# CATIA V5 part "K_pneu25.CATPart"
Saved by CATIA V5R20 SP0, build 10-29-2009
Part number: pneu 25
Publications: "rayon pneu", "largeur pneu", "rayon congé", "Plan.+100", "pneu 25"
Bounding box of the stored display mesh (mm): x 100 to 300, y 820 to 1300, z -240 to 240
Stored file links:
  G:\Khaled_CFAO_2011\SIL\SIL_GR2\mdardier\Khaled\CAD_ThinkMOTION\K_pneu25.CATPart
  G:\Khaled_CFAO_2011\SIL\SIL_GR2\mdardier\Khaled\CAD_ThinkMOTION\K_ass_tandem.CATProduct
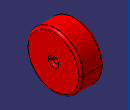
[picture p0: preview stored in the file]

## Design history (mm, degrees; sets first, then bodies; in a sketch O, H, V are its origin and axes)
External parameters (linked from other documents)
  `External.rayon pneu` = 240 mm
  `External.largeur pneu` = 200 mm
  `External.rayon congé` = 20 mm
  `External.demi largeur balancier` = 50 mm
Set1
  Plane1 "Plan.+100": linked copy from another document
  Point1 "pneu 25": linked copy from another document
Body1 (main body)
  Sketch1 on Plane1, origin (100, 0, 0), H (0, 1, 0), V (0, 0, 1)
    circle A1 centre (1060, 0) radius 25
    point P1 (1060, 0)
    reference projected point E1 (1060, 0) from Point1
    circle A2 centre (1060, 0) radius 240
    point P2 (1060, 0)
    reference projected point E2 (1060, 0) from Point1
    radius A2 = 240 {= `External.rayon pneu`}
    radius A1 = 25 {= `External.demi largeur balancier` /2}
    coincidence: P1 E1, P2 E2
  Pad1: profile Sketch1, direction (1, 0, 0), length 200 {= `External.largeur pneu`}
  Fillet1: radius 20 {= `External.rayon congé`}, on end face of Pad1; start face of Pad1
